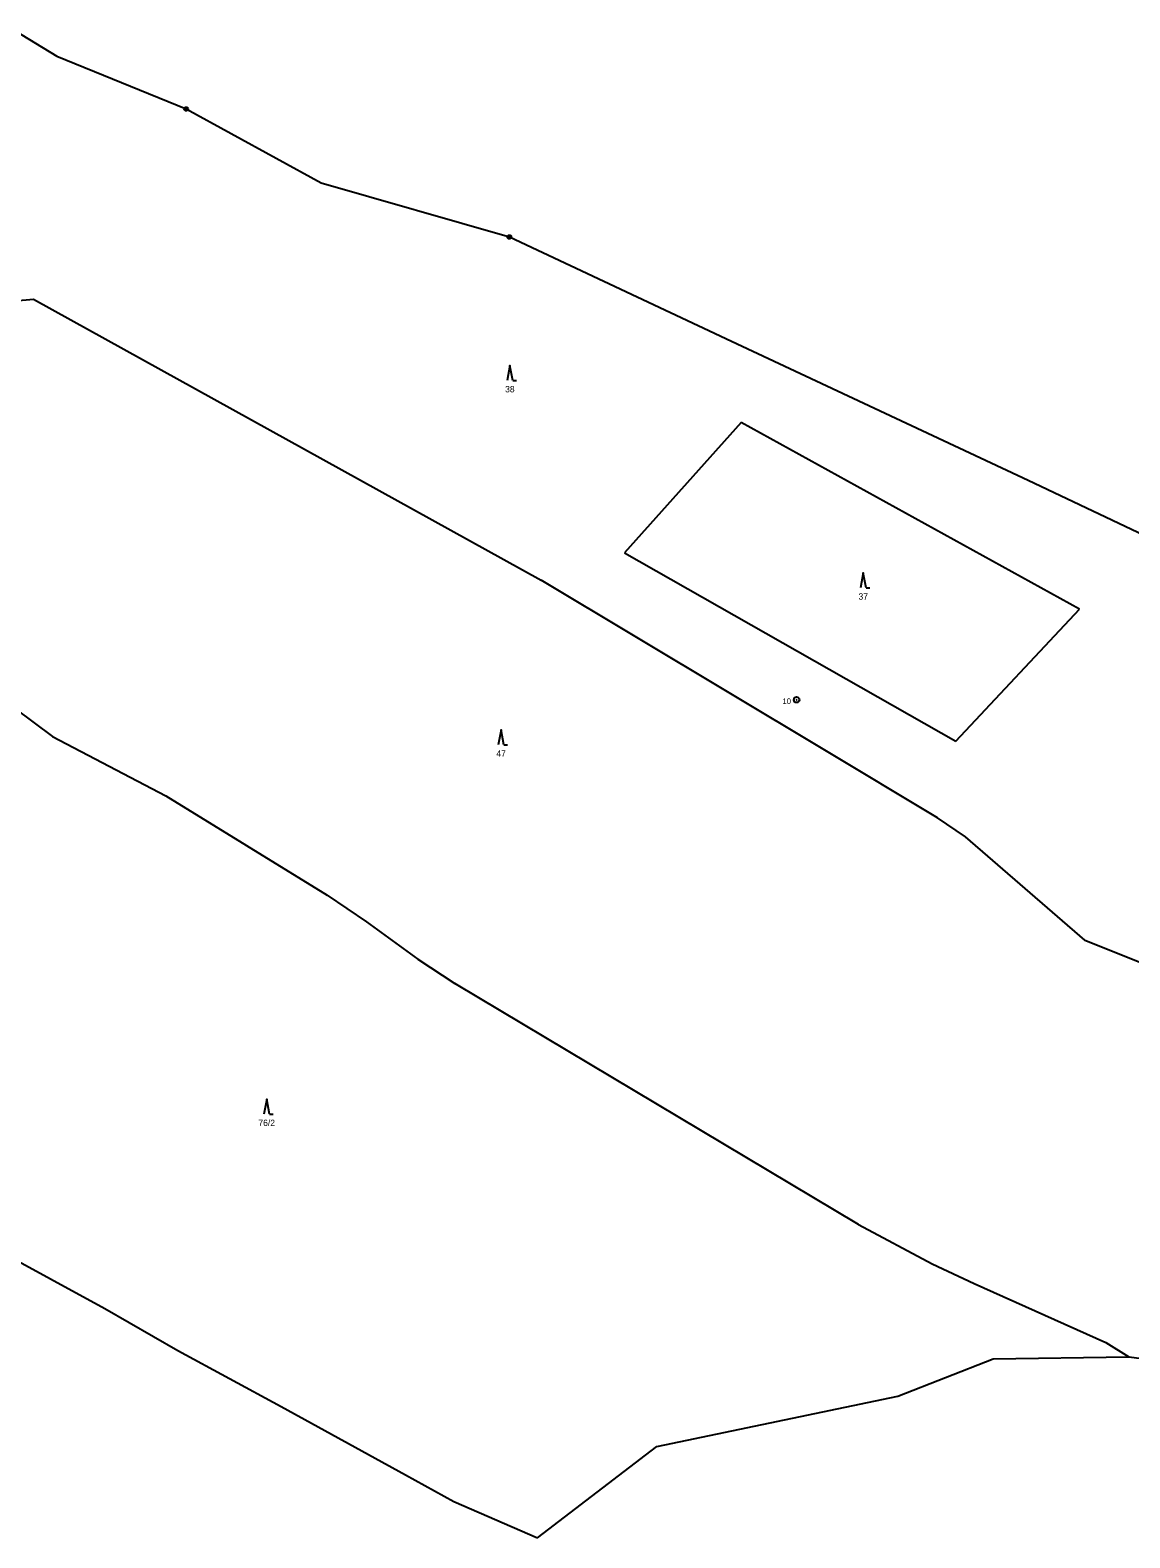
# Model space of a CAD drawing. Extents: x -601877 to -599786, y -1122905 to -1121218.
# Drawn here: x -600789 to -600496.9, y -1121698.1 to -1121297.5 of the extents above; entities that cross this region are included whole.
import ezdxf
from ezdxf.enums import TextEntityAlignment as Align

# ---------------------------------------------------------------- set-up
doc = ezdxf.new("R2010")
doc.units = 0
doc.header["$LTSCALE"] = 0.68
for name, color, linetype, lineweight in [('1', 7, 'Continuous', 25), ('3', 7, 'Continuous', 25), ('8', 7, 'Continuous', 25)]:
    doc.layers.add(name, color=color, linetype=linetype, lineweight=lineweight)
doc.layers.add('2', color=7, linetype='Continuous')

msp = doc.modelspace()

# ---------------------------------------------------------------- linework, layer by layer
at = {"layer": '1'}
for p, q in [((-600793.24, -1121297.49), (-600781.88, -1121304.42)), ((-600781.88, -1121304.42), (-600747.52, -1121318.43)), ((-600747.52, -1121318.43), (-600711.65, -1121338.08)), ((-600711.65, -1121338.08), (-600661.69, -1121352.43)), ((-600661.69, -1121352.43), (-600602.67, -1121380.11)), ((-600810.87, -1121371.03), (-600788.07, -1121368.99)), ((-600788.07, -1121368.99), (-600653.25, -1121443.61)), ((-600600.15, -1121401.69), (-600631.13, -1121436.34)), ((-600510.3, -1121451.29), (-600600.15, -1121401.69)), ((-600631.13, -1121436.34), (-600543.11, -1121486.4)), ((-600578.31, -1121488.55), (-600653.25, -1121443.61)), ((-600543.11, -1121486.4), (-600510.3, -1121451.29)), ((-600814.18, -1121462.04), (-600783.07, -1121485.12)), ((-600783.07, -1121485.12), (-600752.91, -1121500.94)), ((-600548.03, -1121506.78), (-600578.31, -1121488.55)), ((-600752.91, -1121500.94), (-600710.04, -1121527.32)), ((-600540.56, -1121511.82), (-600548.03, -1121506.78)), ((-600508.89, -1121539.27), (-600540.56, -1121511.82)), ((-600710.04, -1121527.32), (-600699.67, -1121534.36)), ((-600699.67, -1121534.36), (-600685.96, -1121544.28)), ((-600508.89, -1121539.27), (-600467.47, -1121555.73)), ((-600685.96, -1121544.28), (-600676.21, -1121550.74)), ((-600569, -1121614.77), (-600676.21, -1121550.74)), ((-600811.04, -1121614.33), (-600769.16, -1121637.1)), ((-600569, -1121614.77), (-600549.37, -1121625.24)), ((-600549.37, -1121625.24), (-600538.29, -1121630.45)), ((-600538.29, -1121630.45), (-600503.29, -1121646.18)), ((-600769.16, -1121637.1), (-600749.71, -1121648.3)), ((-600503.29, -1121646.18), (-600497.18, -1121649.98)), ((-600749.71, -1121648.3), (-600722.31, -1121663.16)), ((-600558.54, -1121660.42), (-600533.18, -1121650.46)), ((-600533.18, -1121650.46), (-600497.18, -1121649.98)), ((-600497.18, -1121649.98), (-600490.27, -1121650.88)), ((-600722.31, -1121663.16), (-600689.26, -1121681.32)), ((-600622.56, -1121673.79), (-600558.54, -1121660.42)), ((-600654.18, -1121698.06), (-600622.56, -1121673.79)), ((-600689.26, -1121681.32), (-600676.47, -1121688.4)), ((-600676.47, -1121688.4), (-600654.18, -1121698.06))]:
    msp.add_line(p, q, dxfattribs=at)
msp.add_lwpolyline([(-600602.67, -1121380.11), (-600523.89, -1121417.05), (-600479.25, -1121438.23)], dxfattribs=at)
at = {"layer": '3'}
for p, q in [((-600660.81, -1121390.6), (-600659.814, -1121390.6)), ((-600566.96, -1121445.68), (-600565.964, -1121445.68)), ((-600663.14, -1121487.4), (-600662.144, -1121487.4)), ((-600725.39, -1121585.52), (-600724.394, -1121585.52))]:
    msp.add_line(p, q, dxfattribs=at)
for points in [[(-600660.81, -1121390.6), (-600661.56, -1121386.6), (-600662.31, -1121390.6)], [(-600566.96, -1121445.68), (-600567.71, -1121441.68), (-600568.46, -1121445.68)], [(-600663.14, -1121487.4), (-600663.89, -1121483.4), (-600664.64, -1121487.4)], [(-600725.39, -1121585.52), (-600726.14, -1121581.52), (-600726.89, -1121585.52)]]:
    msp.add_lwpolyline(points, dxfattribs=at)
at = {"layer": '8'}
for centre, radius in [((-600747.52, -1121318.4299), 0.5), ((-600747.52, -1121318.4299), 0.0303), ((-600661.69, -1121352.4299), 0.5), ((-600661.69, -1121352.4299), 0.0303), ((-600585.4, -1121475.4098), 0.75), ((-600585.4, -1121475.4098), 0.03)]:
    msp.add_circle(centre, radius, dxfattribs=at)

# ---------------------------------------------------------------- texts
at = {"layer": '2'}
for s, p in [('38', (-600661.559, -1121393.725)), ('37', (-600567.709, -1121448.805)), ('47', (-600663.889, -1121490.525)), ('76/2', (-600726.139, -1121588.645))]:
    msp.add_text(s, height=1.7, dxfattribs=at).set_placement(p, align=Align.CENTER)
at = {"layer": '8'}
msp.add_text('10', height=1.5, dxfattribs=at).set_placement((-600586.899, -1121476.527), align=Align.RIGHT)

doc.saveas('drawing.dxf')
